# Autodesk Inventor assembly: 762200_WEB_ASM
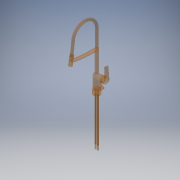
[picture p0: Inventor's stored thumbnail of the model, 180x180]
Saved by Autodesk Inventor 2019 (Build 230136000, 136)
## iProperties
Created: 2018-08
Part Number: 762200_WEB_ASM
Document SubType Name: Assembly
Designer: jaj
Sending System: CREO PARAMETRIC BY PTC INC, 2017380
Preprocessor: CREO PARAMETRIC BY PTC INC, 2017380
Title: 762200_WEB_ASM
Author: jaj
Revision Number: 1LAST_VERSION
Part Number: 65128_WEB
Material: Generic
Document SubType Name: Modeling
Density: 1 g/cm^3
Appearance: Default
Part Number: 48425_WEB
cw_connection: 0:0:1 ul
cwfu: 0:0:
description: 0:0:KITCHEN MIXER
hw_connection: 0:0:1 ul
hwfu: 0:0:
manufacturer: 0:0:FM Mattsson Mora Group
model: 0:0:
url: 0:0:www.damixa.com
vent_connection: 0:0:
waste_connection: 0:0:
wfu: 0:0:
allow_slope_adjustment: 0 ul
connection_type: 14 ul
flow_configuration: 1 ul
flow_direction: 0 ul
loss_method: 0 ul
radius: 5,000 mm
Part Number: 762200_web
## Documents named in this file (5)
- **J:\Engineering\Publish - Read only\FTArkiv\3D filer\762200_web.iam*LocalDocs*xKxvvh03q1mhbulwzQh4slxcqSb*762200_WEB_ASM.iam
- **J:\Engineering\Publish - Read only\FTArkiv\3D filer\762200_web.iam*LocalDocs*xWydnjpb45abeuv0r15u4wdddAg*48425_WEB.ipt
- **J:\Engineering\Publish - Read only\FTArkiv\3D filer\762200_web.iam*LocalDocs*xK23uifwlMe21ekczIuguqukoUf*65128_WEB.ipt
- J:\Engineering\Publish - Read only\FTArkiv\3D filer\762200_web.iam
- J:\Engineering\Publish - Read only\FTArkiv\3D filer\762200_web_asm.stp
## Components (1 placed, 1 different names)
1. 762200_WEB_ASM:1 [sub-assembly]
